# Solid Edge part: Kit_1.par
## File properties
Sűrűség: 0,000 kg/m^3
Pontosság: 0,990
Author: ahadarics
Last saved by: psaghy
Revision: 77
Username: ahadarics
Dokumentum tartalom típus: 0
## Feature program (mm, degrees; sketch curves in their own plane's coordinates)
base feature "unnamed BaseFeature 1"
sketch for "Furat_1" plane through (0, 0, 65) normal (0, 0, 1) x-axis (-1, 0, 0)
  hole centre (-135, 135) bore radius 10.376
hole "Furat_1" nominal diameter 24 finite  ThreadDepth = 28 mm
sketch for "unnamed Hole 1" plane through (0, 0, 65) normal (0, 0, 1) x-axis (-1, 0, 0)
  hole centre (135, -135) bore radius 10.376
hole "unnamed Hole 1" finite
sketch for "unnamed Hole 2" plane through (0, 0, 65) normal (0, 0, 1) x-axis (-1, 0, 0)
  hole centre (-135, -135) bore radius 10.376
hole "unnamed Hole 2" finite
sketch for "unnamed Hole 3" plane through (0, 0, 65) normal (0, 0, 1) x-axis (-1, 0, 0)
  hole centre (135, 135) bore radius 10.376
hole "unnamed Hole 3" finite
pattern "unnamed Pattern 1" of "Furat_1", "unnamed Hole 1", "unnamed Hole 2", "unnamed Hole 3"
sketch for "Furat_5" plane through (35, -174, 35) normal (0, -1, 0) x-axis (0, 0, -1)
hole "Furat_5" diameter 33.249 finite  ThreadDepth = 21 mm
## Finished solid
Body 1: solid body, 796 faces, 1858 edges, 1113 vertices, 2 internal voids.
  Faces by surface: cylinder 281, plane 233, spline 103, torus 102, cone 45, sphere 26, swept 5, spun 1
  Edges by curve: line 677, curve on surface 650, circle 481, spline 27, intersection 16, ellipse 7
Bounding box of the edges (mm; curved faces can reach further): 350.000 x 350.000 x 155.000, from (-175, -175, 0) to (175, 175, 155).
Cylindrical faces by radius (mm): R0.0136 x1, R0.0273 x1, R0.0458 x1, R0.0836 x1, R0.1158 x1, R0.203 x1, R0.2328 x1, R0.2342 x1, R0.2376 x1, R0.2399 x1, R0.24 x1, R0.2548 x1, R0.2555 x1, R0.273 x1, R0.2854 x1, R0.2953 x1, R0.2964 x1, R0.3034 x1, R0.3043 x1, R0.3114 x2, R0.3115 x1, R0.3116 x1, R0.315 x1, R0.3217 x1, R0.3258 x1, R0.326 x1, R0.3334 x1, R0.3348 x1, R0.3378 x1, R0.3382 x1, R0.3388 x1, R0.3402 x1, R0.3438 x1, R0.3452 x2, R0.3466 x1, R0.3511 x1, R0.3758 x1, R0.385 x1, R0.3931 x1, R0.396 x1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
Conical faces (half-angle, radius in mm at the cone's reference point): 1.6538 deg R34.25 x1, 2.665 deg R34.6995 x1, 15 deg R33.933 x2, 15.1276 deg R32.9 x1, 17.1276 deg R32.4441 x1, 25.0169 deg R36.81 x1, 27.7122 deg R31.5344 x1, 27.8853 deg R33.6867 x1, 30 deg R38.0774 x1, 45 deg R5.35 x1, 45 deg R5.75 x1, 45 deg R7.9 x1, 45 deg R10.37 x8, 45 deg R11.376 x4, 45 deg R12.75 x4, 45 deg R15.14 x1, 45 deg R19.5 x4, 45 deg R38.5 x4, 45 deg R143.5 x6, 59 deg R6.25 x1
Toroidal faces (ring radius, tube radius in mm): R3 r2 x2, R5 r5 x1, R8.0257 r3.0044 x8, R8.0258 r3.0045 x4, R8.0543 r3.0493 x1, R8.071 r3.0048 x5, R8.1087 r3.0515 x1, R11.5 r1.5 x8, R15 r10 x1, R17 r1 x12, R19 r5 x1, R21 r5 x1, R29 r5 x1, R31 r1.5 x4, R33.9077 r0.25 x1, R34.2 r0.5 x1, R37 r3 x4, R37.3 r0.2 x1, R37.5 r5 x4, R42.5 r10 x8, R44 r6 x1, R51.5 r1.5 x1, R53.5 r1.5 x1, R56.5 r1.5 x1, R58.5 r1.5 x1, R62 r2 x1, R65 r5 x9, R70 r10 x6, R138.9289 r5 x6, R148.0711 r5 x6
Spherical faces by radius (mm): R3 x1, R5 x5, R5.0686 x12, R10 x8
Planar faces by outward normal: +x 19, +y 13, +z 77, -x 16, -y 20, -z 3, oblique 85
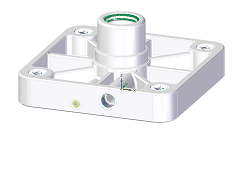
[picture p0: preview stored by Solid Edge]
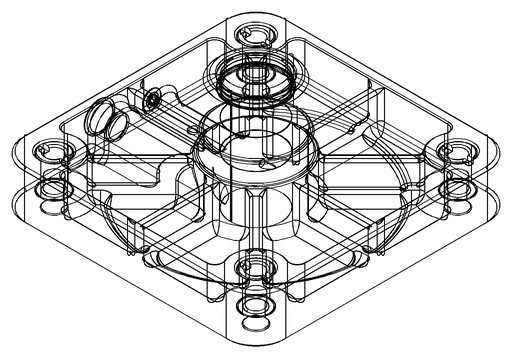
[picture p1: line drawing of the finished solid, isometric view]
